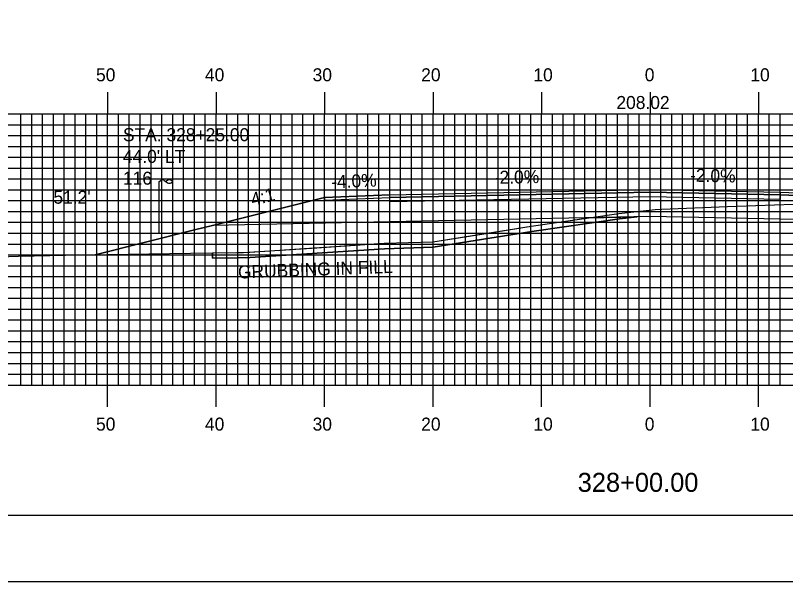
# Model space of a CAD drawing. Extents: x 1821998 to 1822342, y 442591 to 442811.
# Drawn here: x 1822105.8 to 1822176.8, y 442590.5 to 442642.7 of the extents above; entities that cross this region are included whole.
import ezdxf

# ---------------------------------------------------------------- set-up
doc = ezdxf.new("R2010")
doc.units = 0
for name, color, linetype in [('ANNOTATION', 7, 'Continuous'), ('BORDER', 7, 'Continuous'), ('D_Drainage_Text', 7, 'Continuous'), ('D_Roadway_Centerline', 7, 'Continuous'), ('D_Roadway_Centerline_Text', 7, 'Continuous'), ('D_Roadway_Edge_Shoulder', 7, 'Continuous'), ('D_Roadway_Edge_TW', 7, 'Continuous'), ('D_Roadway_Pavement', 7, 'Continuous'), ('D_Roadway_SlopeLines', 7, 'Continuous'), ('D_Roadway_SubGrade', 7, 'Continuous'), ('D_Text_Standard', 7, 'Continuous'), ('D_Utilities_Pole_Joint', 7, 'Continuous'), ('GRUBBING IN FILL', 7, 'Continuous'), ('H_V ANNOTATION', 7, 'Continuous'), ('MAJOR', 7, 'Continuous'), ('MINOR', 7, 'Continuous'), ('PLOT BOUNDARY', 7, 'Continuous'), ('S_Roadway_Centerline', 7, 'Continuous')]:
    doc.layers.add(name, color=color, linetype=linetype)

msp = doc.modelspace()

# ---------------------------------------------------------------- linework, layer by layer
at = {"layer": 'BORDER'}
msp.add_lwpolyline([(1822014.656, 442596.665), (1822334.656, 442596.665), (1822334.656, 442806.665), (1822014.656, 442806.665)], close=True, dxfattribs=at)
at = {"layer": 'D_Roadway_Centerline'}
msp.add_lwpolyline([(1822113.094, 442620.678), (1822122.256, 442622.968), (1822123.908, 442623.381), (1822134.256, 442625.968), (1822140.256, 442626.208), (1822164.256, 442626.688), (1822176.256, 442626.448), (1822184.256, 442626.128), (1822194.43, 442623.585), (1822198.43, 442622.585), (1822210.423, 442625.583), (1822211.673, 442625.859), (1822212.923, 442626.063), (1822214.173, 442626.195), (1822215.423, 442626.254)], dxfattribs=at)
at = {"layer": 'D_Roadway_Edge_Shoulder'}
for points in [[(1822176.256, 442626.448), (1822184.256, 442626.128), (1822184.256, 442625.878), (1822176.256, 442626.198)], [(1822140.256, 442626.208), (1822134.256, 442625.968), (1822134.256, 442625.718), (1822140.256, 442625.958)]]:
    msp.add_lwpolyline(points, close=True, dxfattribs=at)
at = {"layer": 'D_Roadway_Edge_TW'}
msp.add_lwpolyline([(1822140.256, 442625.958), (1822140.256, 442626.208), (1822164.256, 442626.688), (1822176.256, 442626.448), (1822176.256, 442626.198), (1822164.256, 442626.438)], close=True, dxfattribs=at)
at = {"layer": 'D_Roadway_Pavement'}
msp.add_lwpolyline([(1822140.256, 442625.542), (1822140.256, 442625.958), (1822164.256, 442626.438), (1822176.256, 442626.198), (1822176.256, 442625.782), (1822164.256, 442626.022)], close=True, dxfattribs=at)
at = {"layer": 'D_Roadway_SlopeLines'}
msp.add_lwpolyline([(1822134.256, 442625.968), (1822123.908, 442623.381), (1822122.256, 442622.968), (1822113.094, 442620.678)], dxfattribs=at)
at = {"layer": 'D_Roadway_SubGrade'}
msp.add_lwpolyline([(1822140.256, 442623.708), (1822123.908, 442623.381), (1822134.256, 442625.968), (1822134.256, 442625.718), (1822140.256, 442625.958), (1822164.256, 442626.438), (1822176.256, 442626.198), (1822184.256, 442625.878), (1822184.256, 442626.128), (1822194.43, 442623.585), (1822176.256, 442623.948), (1822164.256, 442624.188)], close=True, dxfattribs=at)
at = {"layer": 'D_Utilities_Pole_Joint'}
for p, q in [((1822119.006, 442627.423), (1822119.162, 442627.533)), ((1822119.006, 442622.665), (1822119.006, 442627.423)), ((1822119.475, 442627.533), (1822119.631, 442627.423)), ((1822119.787, 442627.533), (1822119.631, 442627.423)), ((1822119.631, 442627.423), (1822119.787, 442627.312)), ((1822120.256, 442627.423), (1822120.1, 442627.533)), ((1822120.1, 442627.312), (1822120.256, 442627.423)), ((1822120.256, 442622.665), (1822120.256, 442627.423))]:
    msp.add_line(p, q, dxfattribs=at)
for centre, start, end in [((1822119.318, 442627.312), 90, 125.26439), ((1822119.318, 442627.312), 54.73561, 90), ((1822119.943, 442627.312), 90, 125.26439), ((1822119.943, 442627.533), 234.73561, 270), ((1822119.943, 442627.312), 54.73561, 90), ((1822119.943, 442627.533), 270, 305.26439)]:
    msp.add_arc(centre, 0.271, start, end, dxfattribs=at)
at = {"layer": 'GRUBBING IN FILL'}
msp.add_line((1822123.908, 442620.851), (1822123.908, 442620.351), dxfattribs=at)
msp.add_line((1822123.908, 442620.851), (1822123.908, 442620.351), dxfattribs=at)
msp.add_lwpolyline([(1822123.908, 442620.351), (1822126.186, 442620.377), (1822127.394, 442620.418), (1822139.765, 442621.231), (1822144.268, 442621.367), (1822153.363, 442622.816), (1822161.455, 442623.995), (1822163.073, 442624.165)], dxfattribs=at)
msp.add_lwpolyline([(1822123.908, 442620.351), (1822126.186, 442620.377), (1822127.394, 442620.418), (1822139.765, 442621.231), (1822144.268, 442621.367), (1822153.363, 442622.816), (1822161.455, 442623.995), (1822163.073, 442624.165)], dxfattribs=at)
msp.add_lwpolyline([(1822123.908, 442620.851), (1822126.772, 442620.897), (1822133.555, 442621.324), (1822139.741, 442621.731), (1822141.981, 442621.798), (1822144.221, 442621.865), (1822148.754, 442622.588), (1822153.288, 442623.311), (1822157.34, 442623.901), (1822158.529, 442624.074), (1822163.073, 442624.165), (1822162.264, 442624.08), (1822161.455, 442623.995), (1822157.409, 442623.405), (1822153.363, 442622.816), (1822144.268, 442621.367), (1822139.765, 442621.231), (1822133.579, 442620.824), (1822127.394, 442620.418), (1822125.047, 442620.364), (1822123.908, 442620.351)], close=True, dxfattribs=at)
msp.add_lwpolyline([(1822123.908, 442620.851), (1822126.772, 442620.897), (1822133.555, 442621.324), (1822139.741, 442621.731), (1822141.981, 442621.798), (1822144.221, 442621.865), (1822148.754, 442622.588), (1822153.288, 442623.311), (1822157.34, 442623.901), (1822158.529, 442624.074), (1822163.073, 442624.165), (1822162.264, 442624.08), (1822161.455, 442623.995), (1822157.409, 442623.405), (1822153.363, 442622.816), (1822144.268, 442621.367), (1822139.765, 442621.231), (1822133.579, 442620.824), (1822127.394, 442620.418), (1822125.047, 442620.364), (1822123.908, 442620.351)], close=True, dxfattribs=at)
at = {"layer": 'MAJOR'}
for p, q in [((1822114.256, 442635.669), (1822114.256, 442633.665)), ((1822124.256, 442635.669), (1822124.256, 442633.665)), ((1822134.256, 442635.669), (1822134.256, 442633.665)), ((1822144.256, 442635.669), (1822144.256, 442633.665)), ((1822154.256, 442635.669), (1822154.256, 442633.665)), ((1822164.256, 442635.669), (1822164.256, 442633.665)), ((1822174.256, 442635.669), (1822174.256, 442633.665)), ((1822024.256, 442633.665), (1822304.256, 442633.665)), ((1822024.256, 442633.665), (1822304.256, 442633.665)), ((1822114.256, 442608.665), (1822114.256, 442633.665)), ((1822124.256, 442608.665), (1822124.256, 442633.665)), ((1822134.256, 442608.665), (1822134.256, 442633.665)), ((1822144.256, 442608.665), (1822144.256, 442633.665)), ((1822154.256, 442608.665), (1822154.256, 442633.665)), ((1822164.256, 442608.665), (1822164.256, 442633.665)), ((1822174.256, 442608.665), (1822174.256, 442633.665)), ((1822024.256, 442628.665), (1822304.256, 442628.665)), ((1822024.256, 442623.665), (1822304.256, 442623.665)), ((1822024.256, 442618.665), (1822304.256, 442618.665)), ((1822024.256, 442613.665), (1822304.256, 442613.665)), ((1822024.256, 442608.665), (1822304.256, 442608.665)), ((1822024.256, 442608.665), (1822304.256, 442608.665)), ((1822114.256, 442606.661), (1822114.256, 442608.665)), ((1822124.256, 442606.661), (1822124.256, 442608.665)), ((1822134.256, 442606.661), (1822134.256, 442608.665)), ((1822144.256, 442606.661), (1822144.256, 442608.665)), ((1822154.256, 442606.661), (1822154.256, 442608.665)), ((1822164.256, 442606.661), (1822164.256, 442608.665)), ((1822174.256, 442606.661), (1822174.256, 442608.665))]:
    msp.add_line(p, q, dxfattribs=at)
at = {"layer": 'MINOR'}
for p, q in [((1822106.256, 442608.665), (1822106.256, 442633.665)), ((1822107.256, 442608.665), (1822107.256, 442633.665)), ((1822108.256, 442608.665), (1822108.256, 442633.665)), ((1822109.256, 442608.665), (1822109.256, 442633.665)), ((1822110.256, 442608.665), (1822110.256, 442633.665)), ((1822111.256, 442608.665), (1822111.256, 442633.665)), ((1822112.256, 442608.665), (1822112.256, 442633.665)), ((1822113.256, 442608.665), (1822113.256, 442633.665)), ((1822115.256, 442608.665), (1822115.256, 442633.665)), ((1822116.256, 442608.665), (1822116.256, 442633.665)), ((1822117.256, 442608.665), (1822117.256, 442633.665)), ((1822118.256, 442608.665), (1822118.256, 442633.665)), ((1822119.256, 442608.665), (1822119.256, 442633.665)), ((1822120.256, 442608.665), (1822120.256, 442633.665)), ((1822121.256, 442608.665), (1822121.256, 442633.665)), ((1822122.256, 442608.665), (1822122.256, 442633.665)), ((1822123.256, 442608.665), (1822123.256, 442633.665)), ((1822125.256, 442608.665), (1822125.256, 442633.665)), ((1822126.256, 442608.665), (1822126.256, 442633.665)), ((1822127.256, 442608.665), (1822127.256, 442633.665)), ((1822128.256, 442608.665), (1822128.256, 442633.665)), ((1822129.256, 442608.665), (1822129.256, 442633.665)), ((1822130.256, 442608.665), (1822130.256, 442633.665)), ((1822131.256, 442608.665), (1822131.256, 442633.665)), ((1822132.256, 442608.665), (1822132.256, 442633.665)), ((1822133.256, 442608.665), (1822133.256, 442633.665)), ((1822135.256, 442608.665), (1822135.256, 442633.665)), ((1822136.256, 442608.665), (1822136.256, 442633.665)), ((1822137.256, 442608.665), (1822137.256, 442633.665)), ((1822138.256, 442608.665), (1822138.256, 442633.665)), ((1822139.256, 442608.665), (1822139.256, 442633.665)), ((1822140.256, 442608.665), (1822140.256, 442633.665)), ((1822141.256, 442608.665), (1822141.256, 442633.665)), ((1822142.256, 442608.665), (1822142.256, 442633.665)), ((1822143.256, 442608.665), (1822143.256, 442633.665)), ((1822145.256, 442608.665), (1822145.256, 442633.665)), ((1822146.256, 442608.665), (1822146.256, 442633.665)), ((1822147.256, 442608.665), (1822147.256, 442633.665)), ((1822148.256, 442608.665), (1822148.256, 442633.665)), ((1822149.256, 442608.665), (1822149.256, 442633.665)), ((1822150.256, 442608.665), (1822150.256, 442633.665)), ((1822151.256, 442608.665), (1822151.256, 442633.665)), ((1822152.256, 442608.665), (1822152.256, 442633.665)), ((1822153.256, 442608.665), (1822153.256, 442633.665)), ((1822155.256, 442608.665), (1822155.256, 442633.665)), ((1822156.256, 442608.665), (1822156.256, 442633.665)), ((1822157.256, 442608.665), (1822157.256, 442633.665)), ((1822158.256, 442608.665), (1822158.256, 442633.665)), ((1822159.256, 442608.665), (1822159.256, 442633.665)), ((1822160.256, 442608.665), (1822160.256, 442633.665)), ((1822161.256, 442608.665), (1822161.256, 442633.665)), ((1822162.256, 442608.665), (1822162.256, 442633.665)), ((1822163.256, 442608.665), (1822163.256, 442633.665)), ((1822165.256, 442608.665), (1822165.256, 442633.665)), ((1822166.256, 442608.665), (1822166.256, 442633.665)), ((1822167.256, 442608.665), (1822167.256, 442633.665)), ((1822168.256, 442608.665), (1822168.256, 442633.665)), ((1822169.256, 442608.665), (1822169.256, 442633.665)), ((1822170.256, 442608.665), (1822170.256, 442633.665)), ((1822171.256, 442608.665), (1822171.256, 442633.665)), ((1822172.256, 442608.665), (1822172.256, 442633.665)), ((1822173.256, 442608.665), (1822173.256, 442633.665)), ((1822175.256, 442608.665), (1822175.256, 442633.665)), ((1822176.256, 442608.665), (1822176.256, 442633.665)), ((1822024.256, 442632.665), (1822304.256, 442632.665)), ((1822024.256, 442631.665), (1822304.256, 442631.665)), ((1822024.256, 442630.665), (1822304.256, 442630.665)), ((1822024.256, 442629.665), (1822304.256, 442629.665)), ((1822024.256, 442627.665), (1822304.256, 442627.665)), ((1822024.256, 442626.665), (1822304.256, 442626.665)), ((1822024.256, 442625.665), (1822304.256, 442625.665)), ((1822024.256, 442624.665), (1822304.256, 442624.665)), ((1822024.256, 442622.665), (1822304.256, 442622.665)), ((1822024.256, 442621.665), (1822304.256, 442621.665)), ((1822024.256, 442620.665), (1822304.256, 442620.665)), ((1822024.256, 442619.665), (1822304.256, 442619.665)), ((1822024.256, 442617.665), (1822304.256, 442617.665)), ((1822024.256, 442616.665), (1822304.256, 442616.665)), ((1822024.256, 442615.665), (1822304.256, 442615.665)), ((1822024.256, 442614.665), (1822304.256, 442614.665)), ((1822024.256, 442612.665), (1822304.256, 442612.665)), ((1822024.256, 442611.665), (1822304.256, 442611.665)), ((1822024.256, 442610.665), (1822304.256, 442610.665)), ((1822024.256, 442609.665), (1822304.256, 442609.665))]:
    msp.add_line(p, q, dxfattribs=at)
at = {"layer": 'PLOT BOUNDARY'}
msp.add_lwpolyline([(1821998.47, 442590.547), (1822338.47, 442590.547), (1822338.47, 442810.547), (1821998.47, 442810.547)], close=True, dxfattribs=at)
at = {"layer": 'S_Roadway_Centerline'}
msp.add_lwpolyline([(1822093.728, 442620.115), (1822106.051, 442620.561), (1822110.356, 442620.631), (1822121.906, 442620.829), (1822126.175, 442620.877), (1822127.369, 442620.917), (1822139.741, 442621.731), (1822144.221, 442621.865), (1822153.288, 442623.311), (1822161.393, 442624.491), (1822164.725, 442624.841), (1822165.34, 442624.889), (1822171.396, 442625.139), (1822174.885, 442625.262), (1822178.36, 442625.37), (1822192.404, 442625.83), (1822192.502, 442625.834), (1822192.549, 442625.836), (1822192.562, 442625.837), (1822196.653, 442625.818), (1822197.683, 442625.91), (1822199.648, 442625.967), (1822233.122, 442626.575)], dxfattribs=at)

# ---------------------------------------------------------------- texts
at = {"layer": 'ANNOTATION'}
for s, rotation, p in [('-2.0%', 1.14576, (1822149.862, 442627.201)), ('-2.0%', 358.85424, (1822167.942, 442627.415)), ('-4.0%', 2.29061, (1822134.888, 442626.795)), ('4:1', 14.03624, (1822127.618, 442625.17))]:
    msp.add_text(s, height=1.2, rotation=rotation, dxfattribs=at).set_placement(p)
at = {"layer": 'D_Drainage_Text'}
for s, p in [('STA. 328+25.00', (1822115.665, 442631.143)), ("44.0' LT", (1822115.665, 442629.139)), ('116', (1822115.665, 442627.135))]:
    msp.add_text(s, height=1.2, dxfattribs=at).set_placement(p)
at = {"layer": 'D_Roadway_Centerline'}
for s, p in [('C', (1822164.251, 442626.688)), ('L', (1822164.256, 442626.681))]:
    msp.add_text(s, height=0.0146, dxfattribs=at).set_placement(p)
at = {"layer": 'D_Roadway_Centerline_Text'}
msp.add_text('208.02', height=1.2, dxfattribs=at).set_placement((1822161.158, 442634.111))
at = {"layer": 'D_Text_Standard'}
msp.add_text("51.2'", height=1.2, dxfattribs=at).set_placement((1822109.256, 442625.381))
at = {"layer": 'GRUBBING IN FILL'}
msp.add_text('GRUBBING IN FILL', height=1.2, rotation=2.12111, dxfattribs=at).set_placement((1822126.293, 442618.476))
at = {"layer": 'H_V ANNOTATION'}
for s, height, p in [('50', 1.2, (1822113.186, 442636.665)), ('40', 1.2, (1822123.229, 442636.665)), ('30', 1.2, (1822133.154, 442636.665)), ('20', 1.2, (1822143.164, 442636.665)), ('10', 1.2, (1822153.507, 442636.665)), ('0', 1.2, (1822163.774, 442636.665)), ('10', 1.2, (1822173.507, 442636.665)), ('50', 1.2, (1822113.186, 442604.465)), ('40', 1.2, (1822123.229, 442604.465)), ('30', 1.2, (1822133.154, 442604.465)), ('20', 1.2, (1822143.164, 442604.465)), ('10', 1.2, (1822153.507, 442604.465)), ('0', 1.2, (1822163.774, 442604.465)), ('10', 1.2, (1822173.507, 442604.465)), ('328+00.00', 1.75, (1822157.592, 442598.821))]:
    msp.add_text(s, height=height, dxfattribs=at).set_placement(p)

doc.saveas('drawing.dxf')
